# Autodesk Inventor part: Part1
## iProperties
Author: Renu Muthoo
Created: 2001-12
Part Number: Part1
Document SubType Name: Modeling
Designer: Renu Muthoo
Control State: 0
Master: False
Checked Out: False
PropertySet Name: Design Tracking Control
Shininess: 64.0
Angle Display Precision: 2
Document Length Units: 11269
Document Angle Units: 11283
Document Time Units: 11279
Document Mass Units: 11290
Document Length Units Precision: 3
Document Angle Units Precision: 2
Compacted: True
PropertySet Name: _Private Model Information
Density: 0.0
Volumn: 0.0
Area: 0.0
PropertySet Name: Model Information
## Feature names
1. Extrusion1
2. Extrusion2
3. Rectangular Pattern1
4. Shell1
